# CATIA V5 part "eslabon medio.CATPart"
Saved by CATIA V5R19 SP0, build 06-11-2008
Part number: eslabon medio
Bounding box of the stored display mesh (mm): x 215.134 to 240.534, y 422.555 to 1161.855, z 11027.612 to 11260.085
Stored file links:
  E:\Luis\Dropbox\3DIT\Parking\planos\cat 3 dit park8\Cadena\eslabon medio.CATPart
  E:\Luis\Dropbox\3DIT\Parking\planos\cat 3 dit park8\Cadena\Eslabon de Cadena.........................................CATProduct
  E:\Luis\Dropbox\3DIT\Parking\planos\cat 3 dit park8\Cadena\ensamble unico eslabon.CATProduct
  E:\Luis\Dropbox\3DIT\Parking\planos\cat 3 dit park8\Cadena\eslabon entre uniones.CATProduct
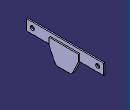
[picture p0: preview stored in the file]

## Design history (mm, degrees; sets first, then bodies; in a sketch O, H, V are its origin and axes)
External parameters (linked from other documents)
  External.p = 625
  External.b1 = 63.5
  External.b2 = 50.8
  External.d2 = 38.1
  External.g = 50.8
Body1 (main body)
  DatumSurface1
  DatumCurve1 to DatumCurve6
  Sketch1 on face of DatumSurface1, origin (227.8342, 0, 0), H (0, -1, 0), V (0, 0, 1)
    point P1 (-1104.7054, 11209.2854)
    point P2 (-479.7054, 11209.2854)
    line L1 (-1161.8554, 11260.0854) -> (-422.5554, 11260.0854)
    line L2 (-422.5554, 11260.0854) -> (-422.5554, 11158.4854)
    line L3 (-422.5554, 11158.4854) -> (-1161.8554, 11158.4854)
    line L4 (-1161.8554, 11158.4854) -> (-1161.8554, 11260.0854)
    reference projected line E1 (-1161.8554, 11234.6854) -> (-1161.8554, 11167.4854) from edge of DatumCurve4
    reference projected line E2 (-615.6554, 11260.0854) -> (-876.0554, 11260.0854) from edge of DatumCurve5
    reference projected line E3 (-876.0554, 11158.4854) -> (-708.2554, 11158.4854) from edge of DatumCurve6
    circle A1 centre (-1104.7054, 11209.2854) radius 19.05
    circle A2 centre (-479.7054, 11209.2854) radius 19.05
    distance L4 E1 = 0
    distance E2 L1 = 0
    distance L3 E3 = 0
    distance P2 P1 = 625 {= External.p /1000}
    distance L2 P2 = 57.15 {= External.d2 *1.5/1000}
    distance L4 P1 = 57.15 {= External.d2 *1.5/1000}
    distance P1 L3 = 50.8 {= External.g /1000}
    radius A2 = 19.05 {= External.d2 /2/1000}
    radius A1 = 19.05 {= External.d2 /1000/2}
    length L3 = 739.3 {= (External.p /1000) +(External.d2 *3/1000)}
    concentricity: P1 A1, P2 A2
    horizontal: L1 H, L3 H
    vertical: L2 V, L4 V
  Pad1: profile Sketch1, direction (-1, 0, 0), length 12.7
  DatumPoint1
  DatumPoint2
  DatumCurve7 to DatumCurve15
  Sketch2 on start face of Pad1, origin (227.8342, 0, 0), H (0, 1, 0), V (0, 0, 1)
    line L1 (652.5554, 11227.2506) -> (931.8554, 11227.2506)
    line L2 (931.8554, 11227.2506) -> (931.8554, 11160.2506)
    line L3 (652.5554, 11160.2506) -> (652.5554, 11227.2506)
    line L4 (732.8691, 11027.6124) -> (789.8096, 11027.6124)
    construction line L5 (792.2054, 11227.2506) -> (792.2054, 11292.1254)
    point P4 (792.2054, 11227.2506)
    reference projected circle E1 centre (479.7054, 11209.2854) radius 19.05 from edge [face of Pad1 from Sketch1.A2 | start face of Pad1]
    construction line L6 (479.7054, 11209.2854) -> (479.7054, 11303.91)
    point P6 (479.7054, 11209.2854)
    reference projected line E2 (460.6554, 11260.0854) -> (1161.8554, 11260.0854) from edge [start face of Pad1 | face of Pad1 from Sketch1.L1]
    reference projected line E3 (1161.8554, 11260.0854) -> (1161.8554, 11158.4854) from edge [start face of Pad1 | face of Pad1 from Sketch1.L4]
    line L7 (931.8554, 11160.2506) -> (874.0115, 11041.6531)
    point P8 (873.9167, 11041.4588)
    point P9 (931.8554, 11160.2506)
    line L8 (710.3993, 11041.6531) -> (652.5554, 11160.2506)
    point P10 (652.5554, 11160.2506)
    point P11 (867.1634, 11027.6124)
    point P13 (717.2474, 11027.6124)
    line L9 (789.8096, 11027.6124) -> (851.5416, 11027.6124)
    reference projected line E4 (1161.8554, 11158.4854) -> (460.6554, 11158.4854) from edge [start face of Pad1 | face of Pad1 from Sketch1.L3]
    arc A1 centre (851.5416, 11052.6124) radius 25 from (874.0115, 11041.6531) to (851.5416, 11027.6124) cw
    arc A2 centre (732.8691, 11052.6124) radius 25 from (732.8691, 11027.6124) to (710.3993, 11041.6531) cw
    distance L5 L6 = 312.5
    distance L1 E2 = 32.8347
    distance L2 E3 = 230
    length L3 = 67
    angle L8 L4 = 116
    angle L9 L7 = 116
    distance P13 L3 = 64.692
    distance P11 E4 = 130.873
    radius A1 = 25
    radius A2 = 25
    horizontal: L1 H
    vertical: L5 V, L6 V, L2 V, L3 V
    concentricity: P6 E1
    midpoint: P4 L1
    coincidence: P9 L7, P8 L7, L7 P11, L9 P11, L4 P13, L8 P13
    symmetry: P13 P11 L5, P10 P9 L5
    tangency: A1 L7, A1 L9, A2 L4, A2 L8
  Pad2: profile Sketch2, direction (1, 0, 0), length 12.7, mirrored extent
  DatumCurve16
  DatumSurface2
  DatumSurface3
  DatumCurve17
  DatumSurface4
  Sketch3 on DatumSurface4, origin (253.2342, 0, 0), H (0, -1, 0), V (0, 0, 1)
    reference projected circle E1 centre (-641.0554, 11209.2854) radius 12.7 from edge of DatumCurve17
    point P1 (-641.0554, 11209.2854)
    concentricity: P1 E1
